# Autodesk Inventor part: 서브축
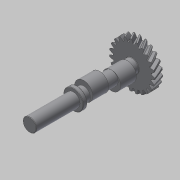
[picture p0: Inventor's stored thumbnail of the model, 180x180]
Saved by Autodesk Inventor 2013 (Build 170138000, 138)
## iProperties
Created: 2016-12
Part Number: 서브축
Material: 강철, 탄소
Document SubType Name: Modeling
Designer: mduedu
Categories: <?xml version="1.0" encoding="UTF-16"?> <MemberInstance><Categories><FamilyTemplate><FamilyTemplateParameter ValueType="xs:double" Id="1" ObjectReferenceKey="da
Density: 7.87 g/cm^3
Mass: 484.101 g
Surface Area: 171.575 cm^2
Volume: 61.5122 cm^3
CustomPartVersion: 1
Author: mduedu
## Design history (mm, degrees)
sketch "Sketch1"
  geometry: C1 r 28.558 at (0, 0)
  constraints: 1 centre point
  dimensions: "d0" = 57.11622 diameter of C1 (= da_da)
extrude "Extrusion1" new body sketch "Sketch1" distance "d1" = 10 (= da_b); taper "d2" = 0 deg
workplane "Work Plane2"
sketch "Sketch2"
  geometry: C1 r 28.558 at (0, 0) reference; C2 r 26.558 at (0, 0)
  constraints: 1 centre point, 1 coincident
  dimensions: "d3" = 53.11622 diameter of C2 (= da_dw)
feature "피치 지름" sketch "Sketch2" dims "d4" = 10, "d5" = 0
workplane "Work Plane8"
workplane "Work Plane9"
feature "스퍼 기어" dims "da_b" = 10, "da_d" = 53.11622, "da_aw" = 43.87862, "da_da" = 57.11622, "da_df" = 48.11622, "da_dw" = 53.11622, angle "da_beta" = 30 deg, "da_lefttooth" = 10, "da_righttooth" = 0
sketch "스케치3"
  geometry: C1 r 12.5 at (0, 0); 1 further point
  constraints: 1 centre point, 1 coincident
  dimensions: "d49" = 25 diameter of C1
extrude "돌출2" join sketch "스케치3" distance "d50" = 6; taper "d51" = 0 deg
sketch "스케치4"
  geometry: C1 r 8.5 at (0, 0); 1 further point
  constraints: 1 centre point, 1 coincident
  dimensions: "d52" = 17 diameter of C1
extrude "돌출3" join sketch "스케치4" distance "d53" = 123; taper "d54" = 0 deg
sketch "스케치5"
  geometry: C1 r 7.5 at (0, 0); 1 further point
  constraints: 1 centre point, 1 coincident
  dimensions: "d55" = 15 diameter of C1
extrude "돌출4" join sketch "스케치5" distance "d56" = 6; taper "d57" = 0 deg
sketch "스케치6"
  geometry: C1 r 4 at (0, 0); 1 further point
  constraints: 1 centre point, 1 coincident
  dimensions: "d58" = 8 diameter of C1
extrude "돌출5" join sketch "스케치6" distance "d59" = 7; taper "d60" = 0 deg
chamfer "모따기1" distance "d61" = 0.5; stored, may be unused: second distance "d62" = 2, angle "d63" = 45 deg
fillet "모깎기1" dims "d64" = 0.5
node "작업 평면11"
sketch "스케치7"
  geometry: C1 r 11.5 at (0, 3); C2 r 8.5 at (0, 0) reference; 1 further point
  constraints: 1 centre point, 1 tangent, 1 vertical alignment
  dimensions: "d66" = 3 distance of point (0, 0) C1.centre; "d67" = 23 diameter of C1 (derived)
extrude "돌출6" join sketch "스케치7" stored distance "d68" = 20; taper "d69" = 0 deg
node "작업 평면13"
sketch "스케치9"
  geometry: C1 r 11.5 at (0, -3); C2 r 8.5 at (0, 0) reference; 1 further point
  constraints: 1 centre point, 1 tangent, 1 vertical alignment
  dimensions: "d78" = 3 distance of C1.centre point (0, 0); "d79" = 23 diameter of C1 (derived)
extrude "돌출8" join sketch "스케치9" stored distance "d80" = 20; taper "d81" = 0 deg
node "작업 평면12"
sketch "스케치8"
  geometry: C1 r 12.5 at (0, 0) reference; 1 further point
extrude "돌출7" join sketch "스케치8" distance "d71" = 5; taper "d72" = 0 deg
chamfer "모따기2" distance "d73" = 0.5; stored, may be unused: second distance "d74" = 2, angle "d75" = 45 deg
sketch "스케치10"
  geometry: C1 r 12.5 at (0, 0) reference; C2 r 8.5 at (0, 0) reference; 1 further point
extrude "돌출9" cut sketch "스케치10" stored distance "d82" = 20; taper "d83" = 0 deg
fillet "모깎기2" dims "d84" = 0.5
body "Solid1"
body "Srf1"
other parameters: "d16" = 43.87862 (= da_aw), "d17" = 0, "d34" = 1.36591 (computed from da_z), "d39" = 0, "d41" = 0, "d43" = 43.87862 (= da_aw), "d46" = 43.87862 (= da_aw), "d47" = 0, "d48" = 0, "d65" = 45, "d70" = 68, "d76" = -35
